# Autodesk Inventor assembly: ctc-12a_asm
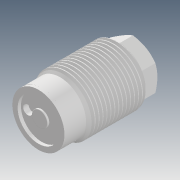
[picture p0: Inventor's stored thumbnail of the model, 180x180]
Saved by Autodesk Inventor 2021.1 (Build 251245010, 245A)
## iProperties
Created: 2010-01
Part Number: ctc-12a_asm
Document SubType Name: Assembly
Designer: user
Title: CTC-12A_ASM
Author: Administrator
Revision Number: 1LAST_VERSION
Sending System: PRO/ENGINEER BY PARAMETRIC TECHNOLOGY CORPORATION, 2007170
Preprocessor: PRO/ENGINEER BY PARAMETRIC TECHNOLOGY CORPORATION, 2007170
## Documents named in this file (6)
- D:\Vault_2016\Projekty\Clamptek\Hydraulic\CTC\Inventor\ctc-12a\ctc-12a_asm.iam
- D:\Vault_2016\Projekty\Clamptek\Hydraulic\CTC\Inventor\ctc-12a\CTC-12ABT.ipt
- D:\Vault_2016\Projekty\Clamptek\Hydraulic\CTC\Inventor\ctc-12a\CTC-12AHSG.ipt
- D:\Vault_2016\Projekty\Clamptek\Hydraulic\CTC\Inventor\ctc-12a\CTC-12AHG.ipt
- D:\Vault_2016\Projekty\Clamptek\Hydraulic\CTC\Inventor\ctc-12a\CTC-12ADP.ipt
- D:\Vault_2016\Projekty\Clamptek\Hydraulic\CTC\Inventor\ctc-12a\CTC-12AMD.ipt
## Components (5 placed, 5 different names)
1. CTC-12ABT_0
2. CTC-12AHSG_1
3. CTC-12AHG_2
4. CTC-12ADP_3
5. CTC-12AMD_4
